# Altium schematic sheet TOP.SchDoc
size A
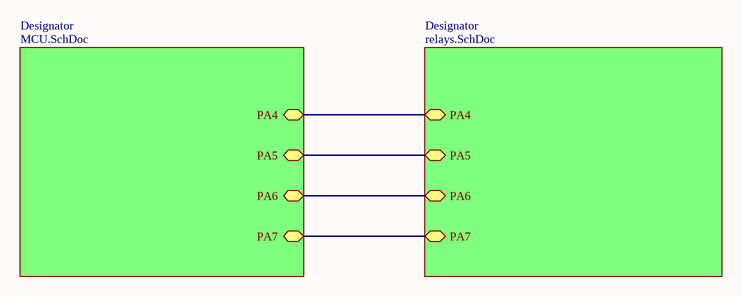
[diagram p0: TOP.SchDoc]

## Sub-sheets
Designator = MCU.SchDoc: PA4, PA5, PA6, PA7
Designator = relays.SchDoc: PA4, PA5, PA6, PA7

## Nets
(unnamed): sheet Designator/PA4, sheet Designator/PA4
(unnamed): sheet Designator/PA5, sheet Designator/PA5  [a separate net that carries the same name]
(unnamed): sheet Designator/PA6, sheet Designator/PA6  [a separate net that carries the same name]
(unnamed): sheet Designator/PA7, sheet Designator/PA7  [a separate net that carries the same name]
